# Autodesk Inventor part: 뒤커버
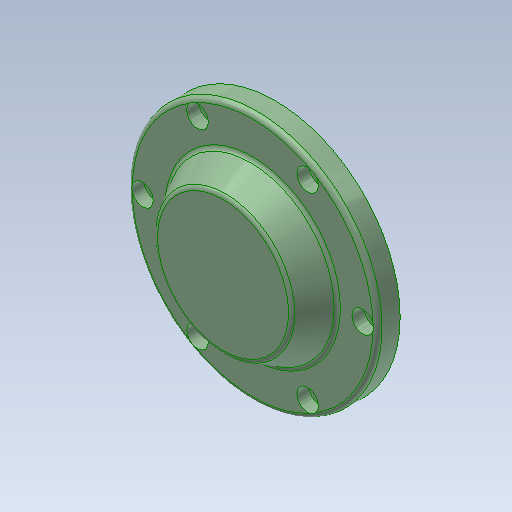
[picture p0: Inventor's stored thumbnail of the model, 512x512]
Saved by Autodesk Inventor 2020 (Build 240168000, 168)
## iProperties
Created: 2013-01
Part Number: 뒤커버
Document SubType Name: Modeling
Designer: 한국산업디자인학원[gmhk.co.kr]
Density: 2.71 g/cm^3
Material: 알루미늄 6061
Mass: 398.51 g
Surface Area: 273.589 cm^2
Volume: 147.052 cm^3
Appearance: 알루미늄 - 평지(1)
Author: 한국산업디자인학원[gmhk.co.kr]
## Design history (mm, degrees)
sketch "스케치2"
  geometry: L1 (-55, 0)-(55, 0) reference; L2 (35.98, -6)-(-35.98, -6) reference; L3 (-42.5, -25)-(-42.5, 0) reference; L4 (-37, -6)-(-37, 0); L5 (-55, 0)-(-55, 10); L6 (-55, 10)-(-37.5, 10); L7 (-37, -6)-(-42.5, -6); L8 (-37.5, 10)-(-29.994, 23); L9 (-29.994, 23)-(0, 23); L10 (-55, 0)-(-42.5, 0); L11 (-42.5, -6)-(-42.5, 0); L12 (0, 0)-(0, 23); L13 (0, 0)-(-37, 0)
  constraints: 22 end point, 4 perpendicular, 3 collinear, 2 parallel, 2 point on line, 1 vertical, 2 other
  dimensions: "d2" = 10 distance of L1.start L5.end; "d4" = 120 deg angle of L8 L6; "d5" = 13 distance between parallel lines of L6 L9; "d6" = 74 diameter of L4 L12; "d7" = 75 diameter of L6.end L12
revolve "회전1" sketch "스케치2" stored, may be unused: angle "d8" = 90 deg
fillet "모깎기1" dims "d9" = 2
sketch "스케치3"
  geometry: C1 r 2.067 at (48.5, 0) reference; 1 further point
hole "구멍1" sketch "스케치3" at (48.5, 0) diameter "d10" = 5.5; stored, may be unused: countersink angle "d14" = 90 deg, drill point angle "d16" = 118 deg; dims "d11" = 6, "d12" = 9.5, "d13" = 5.4, "d15" = 8
fillet "모깎기2" dims "d20" = 3
chamfer "모따기1" distance "d21" = 1; stored, may be unused: second distance "d22" = 2, angle "d23" = 45 deg
node "솔리드1"
pattern_circular "원형 패턴1" dims angle "d18" = 360 deg
node "참조1"
node "참조2"
node "참조3"
